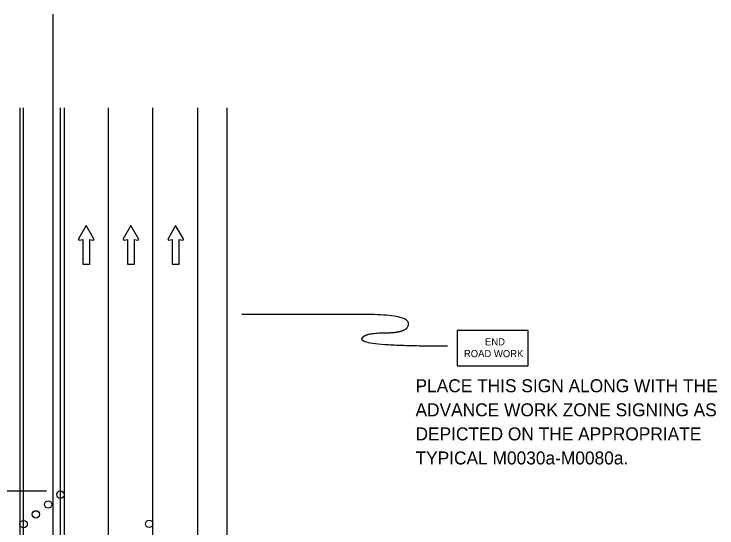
# Model space of a CAD drawing. Extents: x 16731 to 18475, y 7003 to 8262.
# Drawn here: x 17014.2 to 17394, y 7984.8 to 8262.3 of the extents above; entities that cross this region are included whole.
import ezdxf

# ---------------------------------------------------------------- set-up
doc = ezdxf.new("R2010")
doc.units = 0
for name, color, linetype in [('ALI_LEGAL_EX', 7, 'Continuous'), ('MT_SCRATCH_LEVEL_E', 7, 'Continuous'), ('PAVT_EDGE_EX', 7, 'Continuous'), ('TRAFFIC_SIGNS_PR', 7, 'Continuous'), ('TYPICAL_TEXT_DIMEN_PR', 7, 'Continuous')]:
    doc.layers.add(name, color=color, linetype=linetype)

msp = doc.modelspace()

# ---------------------------------------------------------------- linework, layer by layer
at = {"layer": 'ALI_LEGAL_EX'}
for p, q in [((17019.24, 7388.68), (17019.24, 8211.76)), ((17039.24, 7388.68), (17039.24, 8211.76)), ((17065.24, 7388.68), (17065.24, 8211.76)), ((17089.24, 7388.68), (17089.24, 8211.76))]:
    msp.add_line(p, q, dxfattribs=at)
for points in [[(17019.24, 8088.68), (17019.24, 8113.68)], [(17039.24, 8088.68), (17039.24, 8113.68)], [(17065.24, 8088.68), (17065.24, 8113.68)], [(17089.24, 8088.68), (17089.24, 8113.68)], [(17019.24, 7988.68), (17019.24, 8013.68)], [(17039.24, 7988.68), (17039.24, 8013.68)], [(17065.24, 7988.68), (17065.24, 8013.68)], [(17089.24, 7988.68), (17089.24, 8013.68)]]:
    msp.add_lwpolyline(points, dxfattribs=at)
at = {"layer": 'MT_SCRATCH_LEVEL_E'}
for p, q in [((17053.17, 8148.21), (17049.06, 8140.97)), ((17053.17, 8148.21), (17049.06, 8140.97)), ((17057.32, 8140.97), (17053.17, 8148.21)), ((17057.32, 8140.97), (17053.17, 8148.21)), ((17077.34, 8148.21), (17073.23, 8140.97)), ((17077.34, 8148.21), (17073.23, 8140.97)), ((17081.49, 8140.97), (17077.34, 8148.21)), ((17081.49, 8140.97), (17077.34, 8148.21)), ((17101.51, 8148.21), (17097.4, 8140.97)), ((17101.51, 8148.21), (17097.4, 8140.97)), ((17105.66, 8140.97), (17101.51, 8148.21)), ((17105.66, 8140.97), (17101.51, 8148.21)), ((17049.54, 8140.29), (17051.32, 8140.6)), ((17049.54, 8140.29), (17051.32, 8140.6)), ((17051.32, 8140.6), (17051.32, 8127.35)), ((17051.32, 8140.6), (17051.32, 8127.35)), ((17055.06, 8127.35), (17055.06, 8140.6)), ((17055.06, 8140.6), (17056.84, 8140.29)), ((17055.06, 8127.35), (17055.06, 8140.6)), ((17055.06, 8140.6), (17056.84, 8140.29)), ((17073.71, 8140.29), (17075.49, 8140.6)), ((17073.71, 8140.29), (17075.49, 8140.6)), ((17075.49, 8140.6), (17075.49, 8127.35)), ((17075.49, 8140.6), (17075.49, 8127.35)), ((17079.23, 8127.35), (17079.23, 8140.6)), ((17079.23, 8140.6), (17081.01, 8140.29)), ((17079.23, 8127.35), (17079.23, 8140.6)), ((17079.23, 8140.6), (17081.01, 8140.29)), ((17097.88, 8140.29), (17099.66, 8140.6)), ((17097.88, 8140.29), (17099.66, 8140.6)), ((17099.66, 8140.6), (17099.66, 8127.35)), ((17099.66, 8140.6), (17099.66, 8127.35)), ((17103.4, 8127.35), (17103.4, 8140.6)), ((17103.4, 8140.6), (17105.18, 8140.29)), ((17103.4, 8127.35), (17103.4, 8140.6)), ((17103.4, 8140.6), (17105.18, 8140.29)), ((17051.32, 8127.35), (17055.06, 8127.35)), ((17051.32, 8127.35), (17055.06, 8127.35)), ((17075.49, 8127.35), (17079.23, 8127.35)), ((17075.49, 8127.35), (17079.23, 8127.35)), ((17099.66, 8127.35), (17103.4, 8127.35)), ((17099.66, 8127.35), (17103.4, 8127.35))]:
    msp.add_line(p, q, dxfattribs=at)
for centre, start, end in [((17049.47, 8140.75), 150.4248, 279.9638), ((17049.47, 8140.75), 150.4248, 279.9638), ((17056.91, 8140.75), 260.0362, 29.7731), ((17056.91, 8140.75), 260.0362, 29.7731), ((17073.64, 8140.75), 150.4248, 279.9638), ((17073.64, 8140.75), 150.4248, 279.9638), ((17081.08, 8140.75), 260.0362, 29.7731), ((17081.08, 8140.75), 260.0362, 29.7731), ((17097.81, 8140.75), 150.4248, 279.9638), ((17097.81, 8140.75), 150.4248, 279.9638), ((17105.25, 8140.75), 260.0362, 29.7731), ((17105.25, 8140.75), 260.0362, 29.7731)]:
    msp.add_arc(centre, 0.463, start, end, dxfattribs=at)
at = {"layer": 'PAVT_EDGE_EX'}
for p, q in [((17035.15, 8262.34), (17035.15, 7433.15)), ((17017.24, 8211.76), (17017.24, 7353.85)), ((17041.24, 8211.76), (17041.24, 7353.85)), ((17113.24, 8211.76), (17113.24, 7353.85)), ((17129.24, 8211.76), (17129.24, 7353.85))]:
    msp.add_line(p, q, dxfattribs=at)
at = {"layer": 'TRAFFIC_SIGNS_PR'}
msp.add_lwpolyline([(17253.68, 8072.31), (17292.08, 8072.31), (17292.08, 8091.51), (17253.68, 8091.51)], close=True, dxfattribs=at)
for centre in [(17039.23, 8002.77), (17032.6, 7997.46), (17025.97, 7992.14), (17019.34, 7986.82), (17019.34, 7986.82), (17087.21, 7987.06)]:
    msp.add_circle(centre, 2, dxfattribs=at)
at = {"layer": 'TYPICAL_TEXT_DIMEN_PR'}
msp.add_line((16880.24, 8004.8), (17031.69, 8004.8), dxfattribs=at)
msp.add_open_spline([(17248.34, 8082.94), (17202.24, 8082.94), (17202.24, 8090.21), (17227.42, 8090.21), (17227.42, 8100.11), (17177.77, 8100.11), (17137.27, 8100.11)], degree=2, dxfattribs=at)

# ---------------------------------------------------------------- texts
at = {"layer": 'TRAFFIC_SIGNS_PR'}
for s, height, p in [('END', 3.831, (17268.68, 8083.44)), ('ROAD WORK', 3.831, (17257.29, 8077.05)), ('PLACE THIS SIGN ALONG WITH THE', 7, (17231.14, 8058.11)), ('ADVANCE WORK ZONE SIGNING AS', 7, (17231.14, 8045.11)), ('DEPICTED ON THE APPROPRIATE', 7, (17231.14, 8032.11)), ('TYPICAL M0030a-M0080a.', 7, (17231.14, 8019.11))]:
    msp.add_text(s, height=height, dxfattribs=at).set_placement(p)

doc.saveas('drawing.dxf')
